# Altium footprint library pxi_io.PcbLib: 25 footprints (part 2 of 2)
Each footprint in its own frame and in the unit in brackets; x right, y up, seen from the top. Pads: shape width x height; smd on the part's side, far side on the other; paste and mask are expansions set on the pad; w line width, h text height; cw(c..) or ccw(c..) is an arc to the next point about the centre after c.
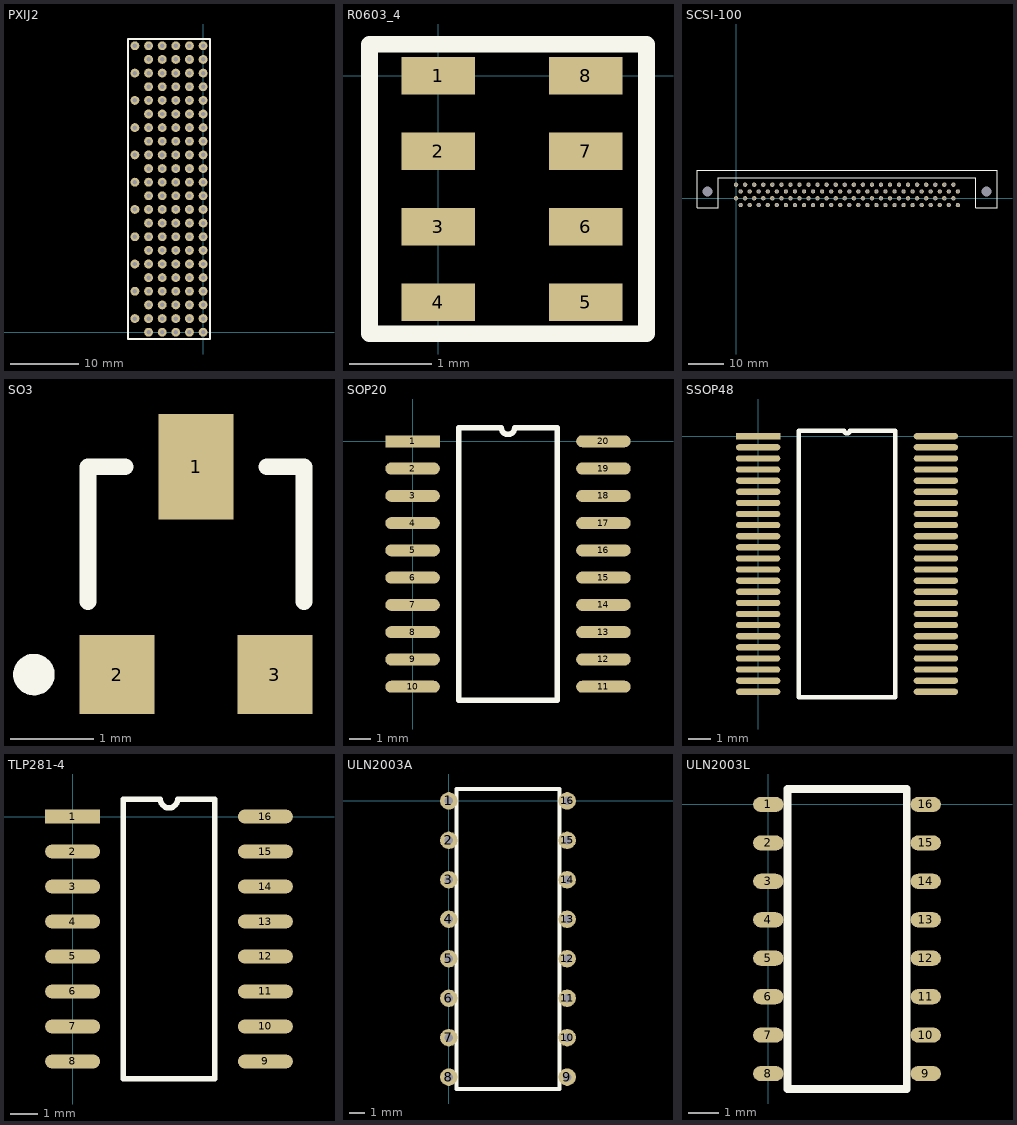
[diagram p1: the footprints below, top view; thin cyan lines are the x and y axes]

## PXIJ2 [mm]
pads (121):
  round 1.3 hole 0.65: A1(0,0) A2(0,2) A3(0,4) A4(0,6) A5(0,8) A6(0,10) A7(0,12) A8(0,14) A9(0,16) A10(0,18) A11(0,20) A12(0,22) A13(0,24) A14(0,26) A15(0,28) A16(0,30) A17(0,32) A18(0,34) A19(0,36) A20(0,38) A21(0,40) A22(0,42) B1(-2,0) B2(-2,2) B3(-2,4) B4(-2,6) B5(-2,8) B6(-2,10) B7(-2,12) B8(-2,14) B9(-2,16) B10(-2,18) B11(-2,20) B12(-2,22) B13(-2,24) B14(-2,26) B15(-2,28) B16(-2,30) B17(-2,32) B18(-2,34) B19(-2,36) B20(-2,38) B21(-2,40) B22(-2,42) C1(-4,0) C2(-4,2) C3(-4,4) C4(-4,6) C5(-4,8) C6(-4,10) C7(-4,12) C8(-4,14) C9(-4,16) C10(-4,18) C11(-4,20) C12(-4,22) C13(-4,24) C14(-4,26) C15(-4,28) C16(-4,30) C17(-4,32) C18(-4,34) C19(-4,36) C20(-4,38) C21(-4,40) C22(-4,42) D1(-6,0) D2(-6,2) D3(-6,4) D4(-6,6) D5(-6,8) D6(-6,10) D7(-6,12) D8(-6,14) D9(-6,16) D10(-6,18) D11(-6,20) D12(-6,22) D13(-6,24) D15(-6,28) D16(-6,30) D17(-6,32) D18(-6,34) D19(-6,36) D20(-6,38) D21(-6,40) D22(-6,42) E1(-8,0) E2(-8,2) E3(-8,4) E4(-8,6) E5(-8,8) E6(-8,10) E7(-8,12) E8(-8,14) E9(-8,16) E10(-8,18) E11(-8,20) E12(-8,22) E13(-8,24) E14(-8,26) E15(-8,28) E16(-8,30) E17(-8,32) E18(-8,34) E19(-8,36) E20(-8,38) E21(-8,40) E22(-8,42) F2(-10,2) F4(-10,6) F6(-10,10) F8(-10,14) F10(-10,18) F12(-10,22) F14(-10,26) F16(-10,30) F18(-10,34) F20(-10,38) F22(-10,42)
  round 1.3 hole 0.73: D14(-6,26)
Top Overlay:
  lines w0.254: -11,-1 1,-1 1,43 -11,43 -11,-1

## R0603_4 [mil] "for ResPackX4____OK!"
pads (8):
  rect 35x18 smd: 1(0,0) 2(0,-36) 3(0,-72) 4(0,-108) 5(70.16,-108) 6(70.16,-72) 7(70.16,-36) 8(70.16,0)
Top Overlay:
  lines w8: -32.84,15 -32.84,-123 99.16,-123 99.16,15 -31.84,15

## SCSI-100 [mm]
pads (102):
  round 1.2 hole 0.85: 1(0,0) 2(1.27,-1.905) 3(2.54,0) 4(3.81,-1.905) 5(5.08,0) 6(6.35,-1.905) 7(7.62,0) 8(8.89,-1.905) 9(10.16,0) 10(11.43,-1.905) 11(12.7,0) 12(13.97,-1.905) 13(15.24,0) 14(16.51,-1.905) 15(17.78,0) 16(19.05,-1.905) 17(20.32,0) 18(21.59,-1.905) 19(22.86,0) 20(24.13,-1.905) 21(25.4,0) 22(26.67,-1.905) 23(27.94,0) 24(29.21,-1.905) 25(30.48,0) 26(31.75,-1.905) 27(33.02,0) 28(34.29,-1.905) 29(35.56,0) 30(36.83,-1.905) 31(38.1,0) 32(39.37,-1.905) 33(40.64,0) 34(41.91,-1.905) 35(43.18,0) 36(44.45,-1.905) 37(45.72,0) 38(46.99,-1.905) 39(48.26,0) 40(49.53,-1.905) 41(50.8,0) 42(52.07,-1.905) 43(53.34,0) 44(54.61,-1.905) 45(55.88,0) 46(57.15,-1.905) 47(58.42,0) 48(59.69,-1.905) 49(60.96,0) 50(62.23,-1.905) 51(0,3.81) 52(1.27,1.905) 53(2.54,3.81) 54(3.81,1.905) 55(5.08,3.81) 56(6.35,1.905) 57(7.62,3.81) 58(8.89,1.905) 59(10.16,3.81) 60(11.43,1.905) 61(12.7,3.81) 62(13.97,1.905) 63(15.24,3.81) 64(16.51,1.905) 65(17.78,3.81) 66(19.05,1.905) 67(20.32,3.81) 68(21.59,1.905) 69(22.86,3.81) 70(24.13,1.905) 71(25.4,3.81) 72(26.67,1.905) 73(27.94,3.81) 74(29.21,1.905) 75(30.48,3.81) 76(31.75,1.905) 77(33.02,3.81) 78(34.29,1.905) 79(35.56,3.81) 80(36.83,1.905) 81(38.1,3.81) 82(39.37,1.905) 83(40.64,3.81) 84(41.91,1.905) 85(43.18,3.81) 86(44.45,1.905) 87(45.72,3.81) 88(46.99,1.905) 89(48.26,3.81) 90(49.53,1.905) 91(50.8,3.81) 92(52.07,1.905) 93(53.34,3.81) 94(54.61,1.905) 95(55.88,3.81) 96(57.15,1.905) 97(58.42,3.81) 98(59.69,1.905) 99(60.96,3.81) 100(62.23,1.905)
  round 2.5 hole 2.77: 101(-8.01,1.905) 102(70.24,1.905)
Top Overlay:
  lines w0.254: -10.975,-2.667 -5.035,-2.667 -5.035,5.715 67.265,5.7 67.265,-2.667 73.205,-2.667 73.205,7.874 -10.975,7.858 -10.975,-2.667

## SO3 [mm]
pads (3):
  rect 0.9x1.27 smd: 1(2.972,-3.601)
  rect 0.9x0.95 smd: 2(2.022,-6.101) 3(3.922,-6.101)
Top Overlay:
  circle w0.25: c1.022,-6.101 r0.125
  lines w0.2: 1.672,-5.226 1.672,-3.601 2.122,-3.601 ; 3.822,-3.601 4.272,-3.601 4.272,-5.226

## SOP20 [mil]
pads (20):
  rect 100x22 smd: 1(0,0)
  oval 100x22 smd: 2(0,-50) 3(0,-100) 4(0,-150) 5(0,-200) 6(0,-250) 7(0,-300) 8(0,-350) 9(0,-400) 10(0,-450) 11(350,-450) 12(350,-400) 13(350,-350) 14(350,-300) 15(350,-250) 16(350,-200) 17(350,-150) 18(350,-100) 19(350,-50) 20(350,0)
Top Overlay:
  lines w10: 85,-475 265,-475 265,25 187.5,25 cw(c175,25) 162.5,25 85,25 85,-475

## SSOP48 [mm]
pads (48):
  rect 2x0.28 smd: 1(0,0)
  oval 2x0.28 smd: 2(0,-0.5) 3(0,-1) 4(0,-1.5) 5(0,-2) 6(0,-2.5) 7(0,-3) 8(0,-3.5) 9(0,-4) 10(0,-4.5) 11(0,-5) 12(0,-5.5) 13(0,-6) 14(0,-6.5) 15(0,-7) 16(0,-7.5) 17(0,-8) 18(0,-8.5) 19(0,-9) 20(0,-9.5) 21(0,-10) 22(0,-10.5) 23(0,-11) 24(0,-11.5) 25(8,-11.5) 26(8,-11) 27(8,-10.5) 28(8,-10) 29(8,-9.5) 30(8,-9) 31(8,-8.5) 32(8,-8) 33(8,-7.5) 34(8,-7) 35(8,-6.5) 36(8,-6) 37(8,-5.5) 38(8,-5) 39(8,-4.5) 40(8,-4) 41(8,-3.5) 42(8,-3) 43(8,-2.5) 44(8,-2) 45(8,-1.5) 46(8,-1) 47(8,-0.5) 48(8,0)
Top Overlay:
  lines w0.2: 1.835,-11.75 1.835,0.25 3.875,0.25 ccw(c4,0.25) 4.125,0.25 6.165,0.25 6.165,-11.75 1.835,-11.75

## TLP281-4 [mm]
pads (16):
  rect 2x0.5 smd: 1(0,0)
  oval 2x0.5 smd: 2(0,-1.27) 3(0,-2.54) 4(0,-3.81) 5(0,-5.08) 6(0,-6.35) 7(0,-7.62) 8(0,-8.89) 9(7,-8.89) 10(7,-7.62) 11(7,-6.35) 12(7,-5.08) 13(7,-3.81) 14(7,-2.54) 15(7,-1.27) 16(7,0)
Top Overlay:
  lines w0.2: 1.835,-9.525 5.165,-9.525 5.165,0.635 3.818,0.635 cw(c3.5,0.635) 3.183,0.635 1.835,0.635 1.835,-9.525

## ULN2003A [mm]
pads (16):
  round 1.12 hole 0.56: 1(0,0) 2(0,-2.54) 3(0,-5.08) 4(0,-7.62) 5(0,-10.16) 6(0,-12.7) 7(0,-15.24) 8(0,-17.78) 9(7.62,-17.78) 10(7.62,-15.24) 11(7.62,-12.7) 12(7.62,-10.16) 13(7.62,-7.62) 14(7.62,-5.08) 15(7.62,-2.54) 16(7.62,0)
Top Overlay:
  lines w0.254: 0.508,-18.542 7.112,-18.542 7.112,0.762 0.508,0.762 0.508,-18.542

## ULN2003L [mm]
pads (16):
  oval 1x0.5 smd: 1(0,0) 2(0,-1.27) 3(0,-2.54) 4(0,-3.81) 5(0,-5.08) 6(0,-6.35) 7(0,-7.62) 8(0,-8.89) 9(5.2,-8.89) 10(5.2,-7.62) 11(5.2,-6.35) 12(5.2,-5.08) 13(5.2,-3.81) 14(5.2,-2.54) 15(5.2,-1.27) 16(5.2,0)
Top Overlay:
  lines w0.254: 0.635,-9.398 4.572,-9.398 4.572,0.508 0.635,0.508 0.635,-9.398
